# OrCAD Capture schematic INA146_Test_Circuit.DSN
size A; title: INA146 High-Voltage Programmable Gain DIFFERENCE AMPLIFIER; rev: 1.1; note: Datasheet: SBOS109  EVM : N/A
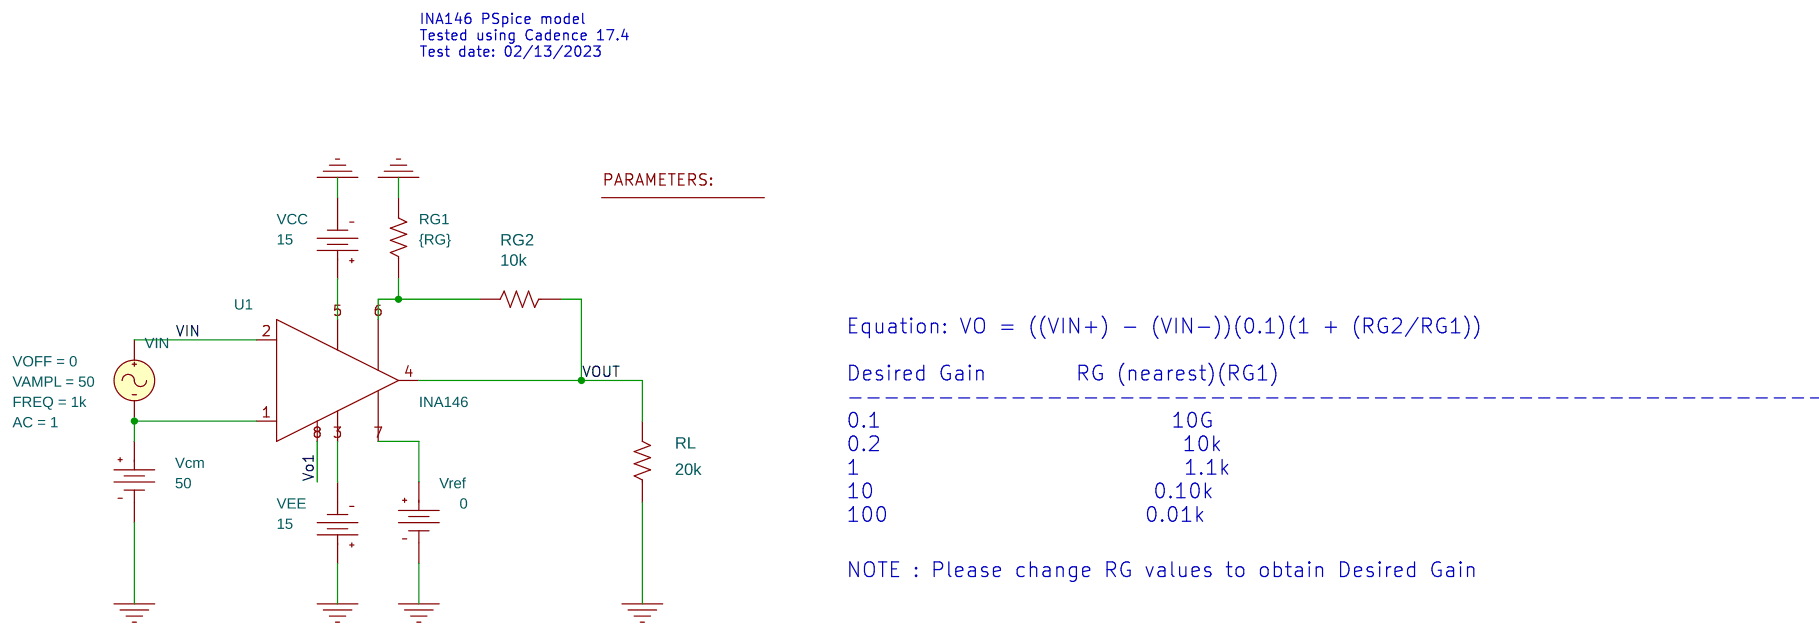
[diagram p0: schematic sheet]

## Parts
1  PARAM
RG1  {RG}  [AX/RC05]
RG2  10k  [AX/RC05]
RL  20k  [AX/RC05]
U1  INA146
VCC  VDC
Vcm  VDC
VEE  VDC
VIN  VSIN
Vref  VDC

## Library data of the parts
1 = PARAM: RG: 10k
RG1 RG2 RL = R
U1 = INA146
VCC VEE = VDC: DC: 15
Vcm = VDC: DC: 50
VIN = VSIN: AC: 1; FREQ: 1k; VAMPL: 50; VOFF: 0
Vref = VDC: DC: 0

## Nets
VIN: U1.2(-) VIN.1(+)
0: RG1.2 RL.1 VCC.1(-) Vcm.1(-) VEE.0(+) Vref.1(-)
Vo1: U1.8(VO1)
VOUT: RG2.1 RL.2 U1.4(OUT)
N14296625: U1.1(+) Vcm.0(+) VIN.2(-)
N14299353: RG1.1 RG2.2 U1.6(RG)
N14300479: U1.5(V+) VCC.0(+)
N14302636: U1.3(V-) VEE.1(-)
N14302867: U1.7(REF) Vref.0(+)

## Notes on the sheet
- INA146 PSpice model
  Tested using Cadence 17.4
  Test date: 02/13/2023
- Equation: VO = ((VIN+) - (VIN-))(0.1)(1 + (RG2/RG1))
  Desired Gain        RG (nearest)(RG1)
  ----------------------------------------------------------
  0.1                          10G
  0.2                           10k
  1                             1.1k
  10                         0.10k
  100                       0.01k
- NOTE : Please change RG values to obtain Desired Gain
